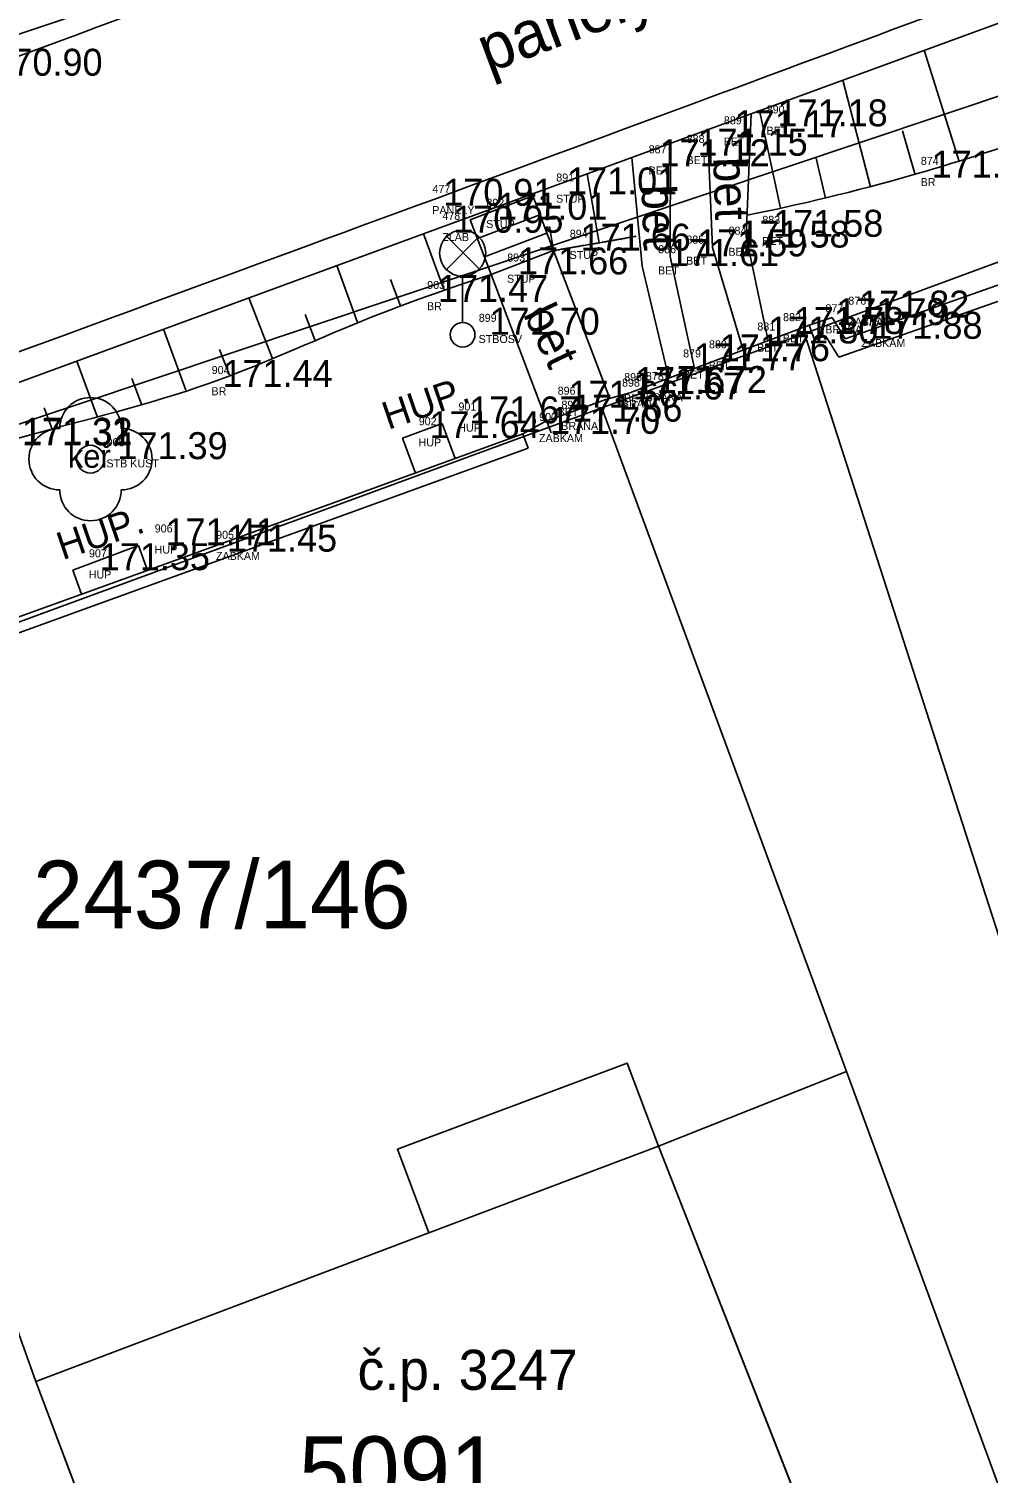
# Model space of a CAD drawing. Extents: x -566117 to -565580, y -1202428 to -1201938.
# Drawn here: x -565871.93 to -565856.36, y -1202054.29 to -1202030.84 of the extents above; entities that cross this region are included whole.
import ezdxf

# ---------------------------------------------------------------- set-up
doc = ezdxf.new("R2010")
doc.units = 0
for name, color, linetype in [('Bod', 7, 'Continuous'), ('BUOVY_NEMĚŘ', 7, 'Continuous'), ('CIZÍ_NADZEM', 7, 'Continuous'), ('Implicitní', 7, 'Continuous'), ('Katastr', 7, 'Continuous'), ('Kod', 7, 'Continuous'), ('Oplocení', 7, 'Continuous'), ('POMOC_POPIS', 7, 'Continuous'), ('Výška', 7, 'Continuous'), ('VÝŠKOPIS (Construction)', 7, 'Continuous'), ('ZELEŇ', 7, 'Continuous'), ('Zpevněné plohy', 7, 'Continuous'), ('Číslo', 7, 'Continuous'), ('Číslo popisné', 7, 'Continuous')]:
    doc.layers.add(name, color=color, linetype=linetype)

# ---------------------------------------------------------------- blocks, each defined once
blk = doc.blocks.new('A$C69D74C1E')
at = {"layer": 'Katastr'}
for p, q in [((175.76, 31.81), (246.67, 55.53)), ((251.13, 50.7), (149.9, 16.82)), ((218.72, 37.49), (205.59, 32.66)), ((202.3, 31.45), (205.59, 32.66)), ((202.3, 31.45), (189.18, 26.63)), ((206.27, 20.67), (202.3, 31.45)), ((206.27, 20.67), (210.24, 9.87)), ((199.49, 18.05), (203.22, 19.46)), ((205.87, 12.71), (203.22, 19.46)), ((193.11, 15.64), (195.47, 9.38))]:
    blk.add_line(p, q, dxfattribs=at)
for points in [[(222.68, 26.7), (219.43, 25.51), (209.12, 21.71), (205.59, 32.66)], [(189.18, 26.63), (193.11, 15.64), (199.49, 18.05), (198.98, 19.41), (202.71, 20.81), (203.22, 19.46), (206.27, 20.67)]]:
    blk.add_lwpolyline(points, dxfattribs=at)
for s, p in [('2437/146', (193.06, 22.997)), ('5091', (197.38, 13.647))]:
    blk.add_text(s, height=1.1, dxfattribs=at).set_placement(p)
blk = doc.blocks.new('6.010')
at = {"layer": 'CIZÍ_NADZEM'}
blk.add_circle((0, -0.001), 0.45, dxfattribs=at)
blk = doc.blocks.new('3.130')
at = {"layer": 'ZELEŇ'}
blk.add_circle((0, 0), 0.001, dxfattribs=at)
for centre, start, end in [((0, 1), 0, 180), ((-1, 0), 90, 270), ((1, 0), 270, 90), ((0, -1), 180, 360)]:
    blk.add_arc(centre, 1, start, end, dxfattribs=at)
blk.add_text('keř', height=0.75, dxfattribs=at).set_placement((-0.737, -0.28))
blk = doc.blocks.new('6.560')
at = {"layer": 'CIZÍ_NADZEM'}
for p, q in [((-0.528, 2.124), (0.528, 3.18)), ((0.544, 2.13), (-0.512, 3.188)), ((0, 1.9), (0, 0.4))]:
    blk.add_line(p, q, dxfattribs=at)
for centre, radius in [((0, 2.65), 0.75), ((0, 0), 0.4)]:
    blk.add_circle(centre, radius, dxfattribs=at)
blk = doc.blocks.new('POINT_DISPLAY')
at = {"layer": 'Implicitní'}
blk.add_line((0, 0), (0, 0), dxfattribs=at)

msp = doc.modelspace()

# ---------------------------------------------------------------- linework, layer by layer
at = {"layer": 'BUOVY_NEMĚŘ'}
for points in [[(-565869.46, -1202059.06), (-565871.82, -1202052.8), (-565865.44, -1202050.39), (-565865.95, -1202049.03), (-565862.22, -1202047.63)], [(-565869.46, -1202059.06), (-565871.82, -1202052.8), (-565865.44, -1202050.39), (-565865.95, -1202049.03), (-565862.22, -1202047.63), (-565861.71, -1202048.98), (-565859.06, -1202055.73), (-565865.95, -1202058.43), (-565866.21, -1202057.78), (-565869.46, -1202059.06)]]:
    msp.add_lwpolyline(points, dxfattribs=at)
at = {"layer": 'Implicitní'}
for p, q in [((-565865.866, -1202037.482), (-565865.222, -1202037.243)), ((-565865.222, -1202037.243), (-565865.013, -1202037.813)), ((-565865.866, -1202037.482), (-565865.658, -1202038.053)), ((-565871.222, -1202039.626), (-565870.153, -1202039.223)), ((-565870.153, -1202039.223), (-565870.006, -1202039.631)), ((-565871.222, -1202039.626), (-565871.081, -1202040.018))]:
    msp.add_line(p, q, dxfattribs=at)
at = {"layer": 'Oplocení'}
for p, q in [((-565858.677, -1202035.868), (-565851.414, -1202033.316)), ((-565851.327, -1202033.551), (-565858.785, -1202036.168)), ((-565862.178, -1202036.748), (-565859.262, -1202035.647)), ((-565859.262, -1202035.647), (-565858.891, -1202035.523)), ((-565859.179, -1202035.883), (-565859.262, -1202035.647)), ((-565858.891, -1202035.523), (-565858.677, -1202035.868)), ((-565859.179, -1202035.883), (-565858.999, -1202035.823)), ((-565858.999, -1202035.823), (-565858.785, -1202036.168)), ((-565863.549, -1202037.214), (-565862.566, -1202036.854)), ((-565862.566, -1202036.854), (-565862.178, -1202036.748)), ((-565869.156, -1202039.325), (-565863.912, -1202037.412)), ((-565863.826, -1202037.646), (-565875.145, -1202041.747)), ((-565875.229, -1202041.512), (-565869.156, -1202039.325))]:
    msp.add_line(p, q, dxfattribs=at)
at = {"layer": 'VÝŠKOPIS (Construction)'}
for p, q in [((-565856.827, -1202032.99), (-565857.395, -1202031.183)), ((-565858.269, -1202033.403), (-565858.72, -1202031.668)), ((-565859.729, -1202033.748), (-565860.068, -1202032.162)), ((-565857.545, -1202033.206), (-565857.749, -1202032.493)), ((-565858.997, -1202033.583), (-565859.155, -1202032.916)), ((-565862.676, -1202034.309), (-565862.871, -1202033.189)), ((-565863.414, -1202034.437), (-565863.483, -1202034.043)), ((-565865.192, -1202035.079), (-565865.527, -1202034.163)), ((-565866.596, -1202035.606), (-565866.936, -1202034.68)), ((-565865.898, -1202035.332), (-565866.062, -1202034.906)), ((-565867.983, -1202036.178), (-565868.363, -1202035.205)), ((-565867.292, -1202035.886), (-565867.45, -1202035.473)), ((-565869.387, -1202036.704), (-565869.751, -1202035.714)), ((-565868.679, -1202036.457), (-565868.837, -1202036.044)), ((-565870.824, -1202037.133), (-565871.156, -1202036.23)), ((-565870.104, -1202036.928), (-565870.263, -1202036.516)), ((-565871.554, -1202037.337), (-565871.688, -1202036.987))]:
    msp.add_line(p, q, dxfattribs=at)
at = {"layer": 'Zpevněné plohy'}
for p, q in [((-565865.482, -1202034.146), (-565855.383, -1202030.445)), ((-565860.207, -1202032.213), (-565860.287, -1202034.212)), ((-565861.518, -1202032.693), (-565861.521, -1202034.531)), ((-565860.835, -1202034.387), (-565860.917, -1202032.473)), ((-565861.978, -1202034.688), (-565862.146, -1202032.924)), ((-565864.768, -1202033.935), (-565863.752, -1202033.548)), ((-565863.752, -1202033.548), (-565863.414, -1202034.437)), ((-565864.651, -1202034.242), (-565863.635, -1202033.856)), ((-565864.43, -1202034.823), (-565864.768, -1202033.935)), ((-565874.305, -1202037.387), (-565865.482, -1202034.146)), ((-565864.538, -1202034.54), (-565863.522, -1202034.154)), ((-565860.287, -1202034.212), (-565859.928, -1202035.899)), ((-565864.43, -1202034.823), (-565863.414, -1202034.437)), ((-565863.414, -1202034.437), (-565862.502, -1202036.837)), ((-565861.521, -1202034.531), (-565861.128, -1202036.352)), ((-565860.336, -1202036.053), (-565860.835, -1202034.387)), ((-565861.543, -1202036.508), (-565861.978, -1202034.688)), ((-565864.43, -1202034.823), (-565863.453, -1202037.393)), ((-565863.912, -1202037.412), (-565863.549, -1202037.214)), ((-565863.912, -1202037.412), (-565863.826, -1202037.646))]:
    msp.add_line(p, q, dxfattribs=at)
for points, degree in [([(-566046.233, -1202095.491), (-566045.931, -1202095.393), (-566043.978, -1202094.752), (-566040.389, -1202093.195), (-566035.531, -1202091.756), (-566028.975, -1202089.449), (-566022.404, -1202086.74), (-566013.877, -1202083.764), (-566006.988, -1202080.967), (-565999.231, -1202078.336), (-565993.39, -1202076.098), (-565982.391, -1202071.759), (-565967.94, -1202066.641), (-565949.498, -1202059.811), (-565935.388, -1202054.572), (-565926.049, -1202051.077), (-565917.958, -1202048.181), (-565909.827, -1202045.163), (-565898.95, -1202041.321), (-565888.732, -1202037.388), (-565879.759, -1202034.036), (-565869.081, -1202030.224), (-565859.242, -1202026.317), (-565849.297, -1202023.069), (-565843.932, -1202020.848), (-565836.631, -1202018.501), (-565830.04, -1202016.01), (-565822.89, -1202013.251), (-565816.476, -1202011.009), (-565808.989, -1202007.913), (-565802.143, -1202004.887), (-565798.059, -1202002.759), (-565793.947, -1202000.116), (-565789.34, -1201997.072), (-565785.134, -1201994.185), (-565781.539, -1201991.969), (-565778.045, -1201989.73), (-565773.319, -1201986.775), (-565768.281, -1201983.714), (-565761.544, -1201979.725), (-565754.374, -1201977.005), (-565748.201, -1201974.518), (-565743.713, -1201972.786), (-565741.115, -1201971.759), (-565739.444, -1201971.098)], 3), ([(-565976.764, -1202074.599), (-565975.068, -1202073.996), (-565970.908, -1202072.515), (-565960.65, -1202068.538), (-565946.466, -1202063.528), (-565932.832, -1202058.326), (-565923.028, -1202054.759), (-565915.71, -1202052.273), (-565903.782, -1202047.572), (-565889.735, -1202042.655), (-565875.782, -1202037.425), (-565865.226, -1202033.562), (-565857.124, -1202030.559), (-565849.222, -1202027.615), (-565843.807, -1202025.74), (-565838.67, -1202023.909), (-565834.175, -1202022.242), (-565830.509, -1202020.913), (-565828.358, -1202020.134)], 3), ([(-565860.273, -1202033.863), (-565859.413, -1202033.687), (-565857.722, -1202033.297), (-565854.096, -1202032.103), (-565850.945, -1202030.693), (-565848.598, -1202029.603), (-565848.131, -1202029.386)], 3), ([(-565863.414, -1202034.437), (-565862.967, -1202034.36), (-565862.519, -1202034.283), (-565862.071, -1202034.203)], 2), ([(-565875.229, -1202041.512), (-565875.317, -1202040.989), (-565875.473, -1202040.058), (-565876.002, -1202039.33), (-565876.214, -1202038.844), (-565875.786, -1202038.698), (-565874.734, -1202038.344), (-565872.321, -1202037.487), (-565869.088, -1202036.737), (-565866.489, -1202035.505), (-565864.864, -1202034.967), (-565864.43, -1202034.823)], 3)]:
    msp.add_open_spline(points, degree=degree, dxfattribs=at)

# ---------------------------------------------------------------- block references
at = {"layer": 'Bod'}
for p in [(-565860.215, -1202032.418), (-565860.911, -1202032.595), (-565861.516, -1202032.896), (-565862.132, -1202033.066), (-565857.713, -1202033.253), (-565863.634, -1202033.524), (-565865.643, -1202033.708), (-565864.768, -1202033.935), (-565865.482, -1202034.146), (-565860.287, -1202034.212), (-565863.414, -1202034.437), (-565861.521, -1202034.531), (-565860.835, -1202034.387), (-565861.978, -1202034.688), (-565864.43, -1202034.823), (-565865.73, -1202035.269), (-565859.262, -1202035.647), (-565858.891, -1202035.523), (-565864.891, -1202035.803), (-565860.368, -1202035.944), (-565859.951, -1202035.791), (-565858.677, -1202035.868), (-565861.573, -1202036.38), (-565861.154, -1202036.233), (-565869.228, -1202036.65), (-565862.566, -1202036.854), (-565862.53, -1202036.765), (-565862.178, -1202036.748), (-565863.61, -1202036.987), (-565865.222, -1202037.243), (-565863.549, -1202037.214), (-565865.866, -1202037.482), (-565863.912, -1202037.412), (-565870.934, -1202037.823), (-565870.153, -1202039.223), (-565869.156, -1202039.325), (-565871.222, -1202039.626)]:
    msp.add_blockref('POINT_DISPLAY', p, dxfattribs=at)
at = {"layer": 'CIZÍ_NADZEM', "xscale": 0.5, "yscale": 0.5}
for name, p in [('6.560', (-565864.891, -1202035.803)), ('6.010', (-565870.935, -1202037.823))]:
    msp.add_blockref(name, p, dxfattribs=at)
at = {"layer": 'Implicitní'}
msp.add_blockref('A$C69D74C1E', (-566064.93, -1202068.44), dxfattribs=at)
at = {"layer": 'ZELEŇ', "xscale": 0.5, "yscale": 0.5}
msp.add_blockref('3.130', (-565870.934, -1202037.823), dxfattribs=at)

# ---------------------------------------------------------------- texts
at = {"layer": 'Kod'}
for s, p in [('BET', (-565859.956, -1202032.553)), ('BET', (-565860.652, -1202032.73)), ('BET', (-565861.256, -1202033.031)), ('BET', (-565861.873, -1202033.2)), ('BR', (-565857.454, -1202033.388)), ('STUP', (-565863.374, -1202033.658)), ('PANELY', (-565865.384, -1202033.843)), ('STUP', (-565864.509, -1202034.069)), ('ZLAB', (-565865.222, -1202034.281)), ('BET', (-565860.028, -1202034.346)), ('STUP', (-565863.154, -1202034.572)), ('BET', (-565861.262, -1202034.665)), ('BET', (-565860.576, -1202034.521)), ('BET', (-565861.719, -1202034.823)), ('STUP', (-565864.17, -1202034.958)), ('BR', (-565865.47, -1202035.404)), ('BRANA', (-565859.002, -1202035.782)), ('ZABKAM', (-565858.631, -1202035.658)), ('STBOSV', (-565864.632, -1202035.937)), ('BET', (-565860.109, -1202036.078)), ('BET', (-565859.691, -1202035.926)), ('ZABKAM', (-565858.417, -1202036.002)), ('BET', (-565861.314, -1202036.515)), ('BET', (-565860.894, -1202036.367)), ('BR', (-565868.969, -1202036.785)), ('BRANA', (-565862.306, -1202036.989)), ('BET', (-565862.27, -1202036.899)), ('BRANA', (-565861.918, -1202036.882)), ('BET', (-565863.351, -1202037.121)), ('HUP', (-565864.962, -1202037.377)), ('BRANA', (-565863.29, -1202037.348)), ('HUP', (-565865.607, -1202037.616)), ('ZABKAM', (-565863.652, -1202037.546)), ('STB KUST', (-565870.675, -1202037.957)), ('HUP', (-565869.893, -1202039.357)), ('ZABKAM', (-565868.897, -1202039.46)), ('HUP', (-565870.962, -1202039.761))]:
    msp.add_text(s, height=0.13, dxfattribs=at).set_placement(p)
at = {"layer": 'POMOC_POPIS'}
for s, height, rotation, p in [('panely', 0.75, 20.4762, (-565864.477, -1202031.556)), ('bet', 0.55, 271.9861, (-565860.823, -1202032.926)), ('bet', 0.55, 271.9861, (-565861.988, -1202033.374)), ('bet', 0.55, 295.6453, (-565863.916, -1202035.468)), ('HUP.', 0.45, 18.8387, (-565866.101, -1202037.348)), ('HUP.', 0.45, 18.8387, (-565871.386, -1202039.465))]:
    msp.add_text(s, height=height, rotation=rotation, dxfattribs=at).set_placement(p)
at = {"layer": 'Výška'}
for s, p in [('170.90', (-565872.527, -1202031.596)), ('171.18', (-565859.778, -1202032.418)), ('171.17', (-565860.474, -1202032.595)), ('171.15', (-565861.078, -1202032.896)), ('171.12', (-565861.695, -1202033.066)), ('171.82', (-565857.276, -1202033.253)), ('171.01', (-565863.196, -1202033.524)), ('170.91', (-565865.206, -1202033.708)), ('171.01', (-565864.331, -1202033.935)), ('170.95', (-565865.044, -1202034.146)), ('171.58', (-565859.85, -1202034.212)), ('171.66', (-565862.976, -1202034.437)), ('171.59', (-565861.084, -1202034.531)), ('171.58', (-565860.398, -1202034.387)), ('171.61', (-565861.541, -1202034.688)), ('171.66', (-565863.992, -1202034.823)), ('171.47', (-565865.292, -1202035.269)), ('171.79', (-565858.824, -1202035.647)), ('171.82', (-565858.453, -1202035.523)), ('171.70', (-565864.454, -1202035.803)), ('171.80', (-565859.931, -1202035.944)), ('171.78', (-565859.513, -1202035.791)), ('171.88', (-565858.239, -1202035.868)), ('171.77', (-565861.136, -1202036.38)), ('171.76', (-565860.716, -1202036.233)), ('171.44', (-565868.791, -1202036.65)), ('171.67', (-565862.128, -1202036.854)), ('171.67', (-565862.092, -1202036.765)), ('171.72', (-565861.74, -1202036.748)), ('171.66', (-565863.173, -1202036.987)), ('171.67', (-565864.784, -1202037.243)), ('171.66', (-565863.112, -1202037.214)), ('171.31', (-565872.048, -1202037.6)), ('171.32', (-565872.041, -1202037.589)), ('171.64', (-565865.429, -1202037.482)), ('171.70', (-565863.474, -1202037.412)), ('171.39', (-565870.497, -1202037.823)), ('171.41', (-565869.715, -1202039.223)), ('171.45', (-565868.719, -1202039.325)), ('171.35', (-565870.784, -1202039.626))]:
    msp.add_text(s, height=0.4375, dxfattribs=at).set_placement(p)
at = {"layer": 'Číslo'}
for s, p in [('890', (-565859.953, -1202032.209)), ('889', (-565860.649, -1202032.386)), ('888', (-565861.253, -1202032.687)), ('887', (-565861.87, -1202032.856)), ('874', (-565857.451, -1202033.044)), ('477', (-565865.381, -1202033.499)), ('891', (-565863.371, -1202033.314)), ('892', (-565864.506, -1202033.725)), ('478', (-565865.22, -1202033.937)), ('883', (-565860.025, -1202034.002)), ('894', (-565863.151, -1202034.228)), ('884', (-565860.573, -1202034.177)), ('885', (-565861.259, -1202034.322)), ('893', (-565864.167, -1202034.614)), ('886', (-565861.716, -1202034.479)), ('903', (-565865.467, -1202035.06)), ('876', (-565858.628, -1202035.314)), ('899', (-565864.629, -1202035.593)), ('882', (-565859.688, -1202035.582)), ('877', (-565858.999, -1202035.438)), ('881', (-565860.106, -1202035.734)), ('875', (-565858.414, -1202035.658)), ('880', (-565860.891, -1202036.023)), ('879', (-565861.311, -1202036.171)), ('904', (-565868.966, -1202036.441)), ('895', (-565862.268, -1202036.555)), ('878', (-565861.915, -1202036.539)), ('896', (-565863.348, -1202036.777)), ('898', (-565862.303, -1202036.645)), ('901', (-565864.959, -1202037.033)), ('897', (-565863.287, -1202037.004)), ('902', (-565865.604, -1202037.273)), ('900', (-565863.649, -1202037.202)), ('908', (-565870.672, -1202037.613)), ('906', (-565869.891, -1202039.013)), ('905', (-565868.894, -1202039.116)), ('907', (-565870.959, -1202039.417))]:
    msp.add_text(s, height=0.13, dxfattribs=at).set_placement(p)
at = {"layer": 'Číslo popisné'}
msp.add_text('č.p. 3247', height=0.65, dxfattribs=at).set_placement((-565866.598, -1202052.937))

doc.saveas('drawing.dxf')
